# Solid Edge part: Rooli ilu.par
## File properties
Author: Türk
Template: Iso Part.par
Last saved by: Türk
Revision: 4
Application: Solid Edge
Accuracy: 0,990
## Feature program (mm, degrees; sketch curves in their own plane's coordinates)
pattern "PatternOccurrence_1"  XOffset = 24 deg
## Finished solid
Body 1: solid body, 35 faces, 109 edges, 60 vertices.
  Faces by surface: cylinder 17, plane 16, torus 2
  Edges by curve: circle 79, intersection 30
Bounding box of the edges (mm; curved faces can reach further): 370.000 x 7.500 x 370.000, from (-185, -7.5, -185) to (185, 0, 185).
Cylindrical faces by radius (mm): R5 x15, R165 x1, R185 x1
Toroidal faces (ring radius, tube radius in mm): R171 r6 x1, R179 r6 x1
Planar faces by outward normal: +y 1, -y 15
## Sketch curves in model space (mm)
circle centre (0, -7.5, 0) radius 175
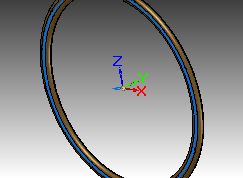
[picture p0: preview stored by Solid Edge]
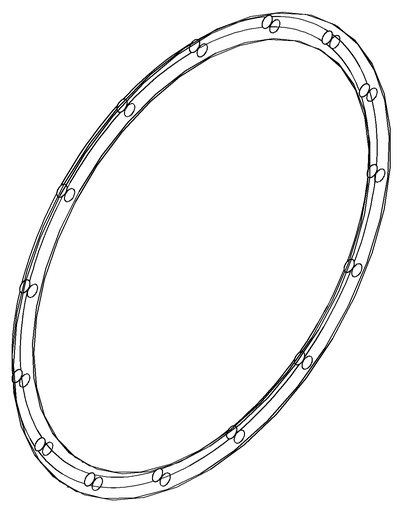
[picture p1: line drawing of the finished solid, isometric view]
